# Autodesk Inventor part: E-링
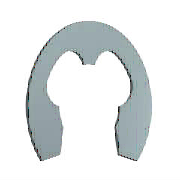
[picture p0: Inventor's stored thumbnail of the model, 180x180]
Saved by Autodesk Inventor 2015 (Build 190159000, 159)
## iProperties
IsCustomPart: 1
Created: 2012-02
Part Number: E-링
Material: 강철, 연강
Description: 리테이닝 링에 대한 사양- 탄소강 E 클립
Document SubType Name: Modeling
Standard: BS 3673-2
Designer: mduedu
Standards Organization: BSI
Language: ko-KR
Size Designation: 032MS
Categories: <MemberInstance><Categories><Category DisplayName="샤프트 부품" InternalName="7f7aeb1f-a693-4053-b835-cee3144e0d98" Mnemonic="SHFT"><Category DisplayName="써클립" Inter
Density: 1 g/cm^3
Appearance: 파란색 - 벽 페인트 - 광택
Author: mduedu
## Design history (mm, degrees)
sketch "스케치1"
  geometry: L1 (-0.4, 0.024)-(0, 0.024) reference; L2 (-3.206, 0)-(3.486, 0) reference; L3 (-1.833, -2.776)-(1.833, -2.776); L4 (0, 1.949)-(0, -3.479) reference; L5 (-2.4, -1.176)-(-2.008, -1.176); L6 (-0.4, 0.424)-(-0.4, 0.812); L7 (0, 1.524)-(2.53, 1.524); L8 (-1.833, -2.776)-(-2.096, -3.394); L9 (0, 0.024)-(-1.278, 0.024); L10 (1.833, -2.776)-(2.096, -3.394); L11 (2.4, -1.176)-(2.008, -1.176); L12 (0.4, 0.424)-(0.4, 0.812); C1 r 2 at (0, -1.976); A1 r 2 centre (0, -1.976) between (-1.894, -1.335) and (-1.833, -2.776); A2 r 0.4 centre (0, 0.424) between (-0.4, 0.424) and (0.4, 0.424); A3 r 3.5 centre (0, -1.976) between (3.196, -3.403) and (-3.196, -3.403); A4 r 3.2 centre (0, -1.976) between (-0.8, 1.122) and (-2.824, -0.47); A5 r 0.32 centre (-0.72, 0.812) between (-0.4, 0.812) and (-0.8, 1.122); A6 r 0.48 centre (-2.4, -0.696) between (-2.824, -0.47) and (-2.4, -1.176); A7 r 0.12 centre (-2.008, -1.296) between (-1.894, -1.335) and (-2.008, -1.176); A8 r 0.6 centre (-2.648, -3.158) between (-3.196, -3.403) and (-2.096, -3.394); A9 r 0.6 centre (2.648, -3.158) between (2.096, -3.394) and (3.196, -3.403); A10 r 2 centre (0, -1.976) between (1.833, -2.776) and (1.894, -1.335); A11 r 0.12 centre (2.008, -1.296) between (2.008, -1.176) and (1.894, -1.335); A12 r 0.48 centre (2.4, -0.696) between (2.4, -1.176) and (2.824, -0.47); A13 r 3.2 centre (0, -1.976) between (2.824, -0.47) and (0.8, 1.122); A14 r 0.32 centre (0.72, 0.812) between (0.8, 1.122) and (0.4, 0.812); 1 further point
  constraints: 30 point on circle, 20 end point, 15 centre point, 13 symmetric about line, 12 tangent, 8 point on line, 4 parallel, 2 coincident, 2 horizontal, 1 concentric, 1 perpendicular, 1 vertical alignment, 9 other
  dimensions: "d0" = 4 diameter of C1 (= WD); "d3" = 0.8 distance from line of A1.centre L3 (= 0.2 x ND); "d4" = 0.4 radius of A2 (= 0.1 x ND); "d5" = 7 diameter of A3 (= SD2); "d8" = 3.2 radius of A4 (= 0.8 x ND); "d9" = 0.8 distance from line of A1.centre L5 (= 0.2 x ND); "d10" = 0.32 radius of A5 (= 0.08 x ND); "d11" = 0.48 radius of A6 (= 0.12 x ND); "d12" = 0.12 radius of A7 (= 0.03 x ND); "d13" = 0.6 radius of A8 (= 0.15 x ND); "d14" = 2 distance from line of A1.centre L9 (= 0.5 x ND); "d15" = 2 radius of A1 (= 0.5 x ND)
extrude "본체" new body sketch "스케치1" distance "d16" = 0.62 (= SD); taper "d17" = 0 deg
workaxis "Work Axis1"
workaxis "Work Axis2"
workplane "Work Plane1"
body "Solid1"
other parameters: "ND" = 4 [user parameter; used in 14 equation terms], "SD" = 0.62 [user parameter; used in 1 equation term], "WD" = 4 (= WDMIN) [user parameter; used in 1 equation term], "d1" = 6.4 (= 1.6 x ND), "d2" = 4 (= ND), "SD2" = 7 [user parameter; used in 1 equation term], "d6" = 4 (= ND), "d7" = 0.6 (= 0.15 x ND), "d18" = 0, "d19" = 0, "d27" = 0, "d28" = 0, "WDMIN" = 4 [user parameter; used in 1 equation term], "SNB" = 0.67 [user parameter], "WDMAX" = 5 [user parameter], "BUBRMI" = 1 [user parameter]
